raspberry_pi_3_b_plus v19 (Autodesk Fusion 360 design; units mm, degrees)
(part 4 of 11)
sketch "Sketch3" plane through (0, 0, 15.35) normal (0, 0, 1) x axis (-1, 0, 0)
  line L1 (-1.7869, -1.625) -> (-1.7869, -4.375)
  line L2 (-7, -3.5135) -> (-1.5412, -4.3781)
  line L3 (-7, -2.4865) -> (-7, -3.5135)
  line L4 (-1.5412, -1.6219) -> (-7, -2.4865)
  line L5 (-1.7303, -1.625) -> (-1.7303, -4.375)
  line L6 (-7.5, -2.3346) -> (-7.5, -3.6654)
  line L7 (-7.2048, -4.0111) -> (-2, -4.8354)
  line L8 (-2, -1.1646) -> (-7.2048, -1.9889)
  line L9 (-2, -4.8354) -> (-1.75, -4.875)
  line L10 (-1.5803, -4.875) -> (-2, -4.875)
  line L11 (-2, -4.875) -> (-1.5803, -4.875)
  line L12 (-1.75, -1.125) -> (-2, -1.1646)
  line L13 (-1.5803, -1.125) -> (-2, -1.125)
  line L14 (-2, -1.125) -> (-2, -1.1646)
  line L15 (-2, -4.8354) -> (-2, -4.875)
  line L16 (-1.7303, 4.375) -> (-1.7303, 1.625)
  line L17 (-11.6332, 0) -> (0, 0)
  line L18 (-2, 4.875) -> (-1.5803, 4.875)
  line L19 (-2, 4.8354) -> (-2, 4.875)
  line L20 (-2, 1.125) -> (-2, 1.1646)
  line L21 (-1.5803, 1.125) -> (-2, 1.125)
  line L22 (-1.75, 1.125) -> (-2, 1.1646)
  line L23 (-2, 4.8354) -> (-1.75, 4.875)
  line L24 (-7, 3.5135) -> (-1.5412, 4.3781)
  line L25 (-7, 2.4865) -> (-7, 3.5135)
  line L26 (-1.5412, 1.6219) -> (-7, 2.4865)
  line L27 (-5, -2.1697) -> (-5, -3.8303)
  line L28
  line L29 (-2.7476, 1.625) -> (-2.7476, 4.375)
  line L30 (-2.7476, -4.375) -> (-2.7476, -1.625)
  line L31 (-7.2048, 1.9889) -> (-2, 1.1646)
  line L32 (-7.5, 3.6654) -> (-7.5, 2.3346)
  line L33 (-2, 4.8354) -> (-7.2048, 4.0111)
  line L34 (-2.0343, 16.7136) -> (-6.9525, 16.1966)
  line L35 (-1.9, 17.5444) -> (-1.9, 16.8627)
  line L36 (-6.9525, 18.2105) -> (-2.0343, 17.6936)
  line L37 (-6.9525, 18.2105) -> (-6.9525, 16.1966)
  line L38 (-6.9525, 17.2036) -> (-1.9, 17.2036)
  line L39 (-1.8477, 18.1753) -> (-6.8739, 18.7036)
  line L40 (-6.8739, 15.7036) -> (-1.8477, 16.2319)
  line L41 (-1.4, 16.7291) -> (-1.4, 17.6781)
  line L42 (-2.0343, -16.7136) -> (-6.9525, -16.1966)
  line L43 (-1.9, -17.5444) -> (-1.9, -16.8627)
  line L44 (-6.9525, -18.2105) -> (-2.0343, -17.6936)
  line L45 (-6.8739, -18.7036) -> (-1.8477, -18.1753)
  line L46 (-1.4, -17.6781) -> (-1.4, -16.7291)
  line L47 (-1.8477, -16.2319) -> (-6.8739, -15.7036)
  line L48 (-3.3296, -16.2022) -> (-3.3296, -18.205)
  line L49 (-7.9, 19.2786) -> (-7.9, 7.1286)
  line L50 (4.3644, 13.2036) -> (-7.9, 13.2036)
  line L51 (-2.0343, 9.6936) -> (-6.9525, 10.2105)
  line L52 (-1.9, 8.8627) -> (-1.9, 9.5444)
  line L53 (-6.9525, 8.1966) -> (-2.0343, 8.7136)
  line L54 (-6.8739, 7.7036) -> (-1.8477, 8.2319)
  line L55 (-1.4, 8.7291) -> (-1.4, 9.6781)
  line L56 (-1.8477, 10.1753) -> (-6.8739, 10.7036)
  line L57 (-1.4, -9.6781) -> (-1.4, -8.7291)
  line L58 (-6.8739, -10.7036) -> (-1.8477, -10.1753)
  line L59 (-1.8477, -8.2319) -> (-6.8739, -7.7036)
  line L60 (-2.0343, -9.6936) -> (-6.9525, -10.2105)
  line L61 (-1.9, -8.8627) -> (-1.9, -9.5444)
  line L62 (-6.9525, -8.1966) -> (-2.0343, -8.7136)
  line L63 (-2, 21.5718) -> (-2, 21.5322)
  line L64 (-7.2048, 22.3961) -> (-2, 21.5718)
  line L65 (-7.5, 24.0725) -> (-7.5, 22.7418)
  line L66 (-2, 25.2426) -> (-7.2048, 24.4182)
  line L67 (-2, 25.2822) -> (-2, 25.2426)
  line L68 (-1.5803, 25.2822) -> (-2, 25.2822)
  line L69 (-1.7303, 24.7822) -> (-1.5803, 24.7822)
  line L70 (-1.7303, 22.0322) -> (-1.7303, 24.7822)
  line L71 (-1.5803, 22.0322) -> (-1.7303, 22.0322)
  line L72 (-2, 21.5322) -> (-1.5803, 21.5322)
  line L73 (-7.9, 20.9572) -> (-7.9, 26.3572)
  line L74 (-7.9, 20.4572) -> (-7.9, 20.9572)
  line L75 (0.28, 20.4572) -> (-7.9, 20.4572)
  line L76 (0.28, 26.3572) -> (0.28, 20.4572)
  line L77 (-7.9, 26.3572) -> (0.28, 26.3572)
  line L78 (-1.7303, 23.4072) -> (-7.5, 23.4072)
  line L79 (-6.7891, 23.9541) -> (-1.5412, 24.7852)
  line L80 (-7, 23.1072) -> (-7, 23.7071)
  line L81 (-1.5412, 22.0291) -> (-6.7891, 22.8603)
  line L82 (-5, 24.2374) -> (-5, 22.5769)
  line L83 (-1.75, 25.2822) -> (-2, 25.2426)
  line L84 (-1.75, 21.5322) -> (-2, 21.5718)
  line L85 (-2.7476, 22.0322) -> (-2.7476, 24.7822)
  line L86 (-6.7891, -23.9541) -> (-1.5412, -24.7852)
  line L87 (-7, -23.1072) -> (-7, -23.7071)
  line L88 (-1.5412, -22.0291) -> (-6.7891, -22.8603)
  line L89 (-5, -24.2374) -> (-5, -22.5769)
  line L90 (-7.9, -20.9572) -> (-7.9, -20.4572)
  line L91 (-7.9, -26.3572) -> (-7.9, -20.9572)
  line L92 (0.28, -26.3572) -> (-7.9, -26.3572)
  line L93 (0.28, -20.4572) -> (0.28, -26.3572)
  line L94 (-7.9, -20.4572) -> (0.28, -20.4572)
  line L95 (-1.5803, -24.7822) -> (-1.7303, -24.7822)
  line L96 (-2, -25.2822) -> (-1.5803, -25.2822)
  line L97 (-2, -25.2426) -> (-2, -25.2822)
  line L98 (-7.2048, -24.4182) -> (-2, -25.2426)
  line L99 (-7.5, -22.7418) -> (-7.5, -24.0725)
  line L100 (-2, -21.5718) -> (-7.2048, -22.3961)
  line L101 (-2, -21.5322) -> (-2, -21.5718)
  line L102 (-1.5803, -21.5322) -> (-2, -21.5322)
  line L103 (-1.7303, -22.0322) -> (-1.5803, -22.0322)
  line L104 (-1.7303, -24.7822) -> (-1.7303, -22.0322)
  line L105 (-1.75, -25.2822) -> (-2, -25.2426)
  line L106 (-2.7476, -24.7822) -> (-2.7476, -22.0322)
  line L107 (-1.75, -21.5322) -> (-2, -21.5718)
  arc A1 centre (-1.5803, -4.625) radius 0.25 clockwise from (-1.5803, -4.375) to (-1.5803, -4.875)
  arc A2 centre (-1.5803, -4.625) radius 0.25 clockwise from (-1.5803, -4.375) to (-1.5803, -4.875)
  arc A3 centre (-1.5803, -1.375) radius 0.25 clockwise from (-1.5803, -1.125) to (-1.5803, -1.625)
  arc A4 centre (-1.5803, 4.625) radius 0.25 clockwise from (-1.5803, 4.875) to (-1.5803, 4.375)
  arc A5 centre (-1.5803, 1.375) radius 0.25 clockwise from (-1.5803, 1.625) to (-1.5803, 1.125)
  arc A6 centre (-6.75, -3.3) radius 0.25 clockwise from (-6.7891, -3.5469) to (-7, -3.3)
  arc A7 centre (-6.75, -2.7) radius 0.25 clockwise from (-7, -2.7) to (-6.7891, -2.4531)
  arc A8 centre (-6.75, 3.3) radius 0.25 clockwise from (-7, 3.3) to (-6.7891, 3.5469)
  arc A9 centre (-6.75, 2.7) radius 0.25 clockwise from (-6.7891, 2.4531) to (-7, 2.7)
  arc A10 centre (-7.15, -3.6654) radius 0.35 clockwise from (-7.2048, -4.0111) to (-7.5, -3.6654)
  arc A11 centre (-7.15, -2.3346) radius 0.35 clockwise from (-7.5, -2.3346) to (-7.2048, -1.9889)
  arc A12 centre (-7.15, 2.3346) radius 0.35 clockwise from (-7.2048, 1.9889) to (-7.5, 2.3346)
  arc A13 centre (-7.15, 3.6654) radius 0.35 clockwise from (-7.5, 3.6654) to (-7.2048, 4.0111)
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  point P10 (-1.5412, -4.3781)
  point P16 (-1.5412, -1.6219)
  point P21 (-2, -4.8354)
  point P24 (-2, -4.8354)
  point P23 (-1.75, -4.875)
  point P22 (-2, -1.1646)
  point P27 (-2, -1.1646)
  point P28 (-1.75, -1.125)
  point P1 (0, 0)
  point P33 (0, 0)
  point P4 (-1.5803, -4.875)
  point P36 (-1.5803, 4.875)
  point P5 (-1.5803, -4.375)
  point P37 (-1.5803, 4.375)
  point P47 (-1.5412, 4.3781)
  point P11 (-7, -3.5135)
  point P48 (-7, 3.5135)
  point P12 (-7, -2.4865)
  point P49 (-7, 2.4865)
  point P13 (-1.5803, -1.625)
  point P52 (-1.5803, 1.625)
  point P14 (-1.5803, -1.125)
  point P53 (-1.5803, 1.125)
  point P50 (-1.5412, 1.6219)
  point P39 (-2, 4.8354)
  point P40 (-2, 1.1646)
  point P45 (-1.75, 4.875)
  point P46 (-2, 4.8354)
  point P26 (-2, -4.875)
  point P38 (-2, 4.875)
  point P43 (-2, 1.1646)
  point P44 (-1.75, 1.125)
  point P29 (-2, -1.125)
  point P41 (-2, 1.125)
  point P30 (-1.5803, -1.125)
  point P42 (-1.5803, 1.125)
  point P54 (-5, -3.8303)
  point P55 (-5, 3.8303)
  point P56 (-5, -2.1697)
  point P57 (-5, 2.1697)
  point P63 (-7, -3.3)
  point P62 (-6.7891, -3.5469)
  point P66 (-7, -2.7)
  point P65 (-6.7891, -2.4531)
  point P70 (-6.7891, 3.5469)
  point P69 (-7, 3.3)
  point P72 (-6.7891, 2.4531)
  point P73 (-7, 2.7)
  point P90 (-6.9525, 16.1966)
  point P91 (-6.9525, 16.1966)
  point P98 (-6.9525, 18.2105)
  point P99 (-6.9525, 18.2105)
  point P102 (-1.9, 17.2036)
  point P103 (-6.9525, 17.2036)
  point P114 (-6.9525, -16.1966)
  point P92 (-2.0343, 16.7136)
  point P115 (-2.0343, -16.7136)
  point P93 (-1.9, 16.8627)
  point P117 (-1.9, -16.8627)
  point P95 (-1.9, 17.5444)
  point P118 (-1.9, -17.5444)
  point P96 (-2.0343, 17.6936)
  point P120 (-2.0343, -17.6936)
  point P121 (-6.9525, -18.2105)
  point P138 (-7.9, 13.2036)
  point P140 (-6.9525, 10.2105)
  point P141 (-2.0343, 9.6936)
  point P143 (-1.9, 9.5444)
  point P144 (-1.9, 8.8627)
  point P146 (-2.0343, 8.7136)
  point P147 (-6.9525, 8.1966)
  point P172 (-6.9525, -10.2105)
  point P173 (-2.0343, -9.6936)
  point P175 (-1.9, -9.5444)
  point P176 (-1.9, -8.8627)
  point P178 (-2.0343, -8.7136)
  point P179 (-6.9525, -8.1966)
  point P203 (-7.5, 23.4072)
  point P204 (-1.7303, 23.4072)
  point P206 (-6.7891, 23.9541)
  point P210 (-6.7891, 22.8603)
  point P213 (-5, 22.5769)
  point P214 (-5, 24.2374)
  point P188 (-2, 25.2426)
  point P215 (-2, 25.2426)
  point P216 (-1.75, 25.2822)
  point P181 (-2, 21.5718)
  point P217 (-2, 21.5718)
  point P218 (-1.75, 21.5322)
  point P205 (-1.5412, 24.7852)
  point P221 (-1.5412, -24.7852)
  point P222 (-6.7891, -23.9541)
  point P207 (-7, 23.7071)
  point P224 (-7, -23.7071)
  point P209 (-7, 23.1072)
  point P225 (-7, -23.1072)
  point P227 (-6.7891, -22.8603)
  point P212 (-1.5412, 22.0291)
  point P228 (-1.5412, -22.0291)
  point P229 (-5, -22.5769)
  point P230 (-5, -24.2374)
  point P241 (-2, -25.2426)
  point P254 (-2, -25.2426)
  point P255 (-1.75, -25.2822)
  point P248 (-2, -21.5718)
  point P258 (-2, -21.5718)
  point P259 (-1.75, -21.5322)
  coincident A1 P10
  coincident A3 P16
  tangent A3 L4
  vertical L3
  tangent A1 L2
  parallel L2 L7
  parallel L4 L8
  coincident P21 P24
  coincident P23 L10
  parallel L7 L9
  coincident P22 P27
  parallel L8 L12
  coincident P28 L13
  coincident P1 P33
  horizontal L17
  symmetric P4 L17 P36
  symmetric P5 L17 P37
  symmetric A1 L17 A4
  symmetric P10 L17 P47
  symmetric P11 L17 P48
  symmetric P12 L17 P49
  symmetric P13 L17 P52
  symmetric P14 L17 P53
  symmetric A3 L17 A5
  symmetric P16 L17 P50
  symmetric P21 L17 P39
  symmetric P22 L17 P40
  symmetric P23 L17 P45
  symmetric P24 L17 P46
  symmetric P26 L17 P38
  symmetric P27 L17 P43
  symmetric P28 L17 P44
  symmetric P29 L17 P41
  symmetric P30 L17 P42
  coincident L2 P54
  coincident L24 P55
  vertical L27
  collinear L27 L28
  coincident L4 P56
  coincident L26 P57
  tangent L2 A6
  coincident L3 P63
  coincident L2 P62
  tangent L3 A6
  tangent L4 A7
  coincident L3 P66
  coincident L4 P65
  tangent L3 A7
  equal A6 A7
  symmetric L17 P62 P70
  symmetric L17 P63 P69
  symmetric L17 A6 A8
  symmetric L17 P65 P72
  symmetric L17 P66 P73
  symmetric L17 A7 A9
  coincident P90 P91
  vertical L35
  coincident P98 P99
  midpoint L35 P102
  midpoint L37 P103
  horizontal L38
  parallel L36 L39
  parallel L34 L40
  symmetric L17 P91 P114
  symmetric L17 P92 P115
  symmetric L17 P93 P117
  symmetric L17 P95 P118
  symmetric L17 P96 P120
  symmetric L17 P99 P121
  midpoint L49 P138
  horizontal L50
  symmetric P91 L50 P140
  symmetric P92 L50 P141
  symmetric P93 L50 P143
  symmetric P95 L50 P144
  symmetric P96 L50 P146
  symmetric P99 L50 P147
  symmetric L17 P140 P172
  symmetric L17 P141 P173
  symmetric L17 P143 P175
  symmetric L17 P144 P176
  symmetric L17 P146 P178
  symmetric L17 P147 P179
  midpoint L65 P203
  midpoint L70 P204
  vertical L80
  symmetric L78 P206 P210
  coincident L81 P213
  coincident L79 P214
  vertical L82
  collinear L3 L80
  parallel L64 L81
  collinear L27 L82
  coincident P188 P215
  parallel L66 L83
  coincident L68 P216
  coincident P181 P217
  parallel L64 L84
  coincident L72 P218
  symmetric L17 P205 P221
  symmetric L17 P206 P222
  symmetric L17 P207 P224
  symmetric L17 P209 P225
  symmetric L17 P210 P227
  symmetric L17 P212 P228
  symmetric L17 P213 P229
  symmetric L17 P214 P230
  coincident P241 P254
  parallel L98 L105
  coincident L96 P255
  coincident P248 P258
  parallel L100 L107
  coincident L102 P259
  dimension "d58_2" distance L3 L6 = 0.5
  dimension "d62_2" distance L25 L27 = 2
  dimension "d67_3" radius A6 = 0.25
  dimension "d133_2" radius = 0.15
  dimension "d227_2" distance L35 L41 = 0.5
  dimension "d386" radius = 0.25 (= "d67_3")
extrude "Extrude1" cut sketch "Sketch3" no distance stored
extrude "Extrude2" add sketch "Sketch3" profile of L2 L4 L9 L10 L11 L12 L13 L14 L15 L18 L19 L20 L21 L22 L23 L24 L26 L28 L29 L30 L63 L67 L68 L72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 to an object
canvas "Canvas2"
sketch "Sketch4" plane through (0, 0, 15.35) normal (0, 0, 1) x axis (-1, 0, 0)
  line L1 (8.5, -21.1878) -> (0.78, -21.1878)
  line L2 (8.5, -6.6286) -> (8.5, -15.9536)
  line L3 (-7.9, -6.6286) -> (8.5, -6.6286)
  line L4 (-7.9, -7.1286) -> (-7.9, -6.6286)
  line L5 (-7.9, -19.2786) -> (-7.9, -7.1286)
  line L6 (-7.9, -19.7786) -> (-7.9, -19.2786)
  line L7 (0.28, -19.7786) -> (-7.9, -19.7786)
  line L8 (0.78, -21.1878) -> (0.78, -19.7786)
  line L9 (7.9563, -25.2118) -> (8.5, -20.7835)
  line L10 (6.5097, -21.514) -> (6.9637, -25.2118)
  line L11 (2.9803, -21.014) -> (6.2597, -21.014)
  line L12 (2.7303, -21.514) -> (2.7303, -21.264)
  line L13 (2.2763, -25.2118) -> (2.7303, -21.514)
  line L14 (0.78, -21.414) -> (0.78, -23.8331)
  line L15 (0.78, -21.1092) -> (1.2837, -25.2118)
  line L16 (7.46, -21.7371) -> (7.46, -25.1508)
  line L17 (8.5, -25.6508) -> (0.78, -25.6508)
  line L18 (6.5097, -21.514) -> (6.5097, -21.264)
  line L19 (1.78, -21.9964) -> (1.78, -25.1508)
  line L20 (0.78, -21.414) -> (8.5, -21.414)
  line L21 (19.0131, 0) -> (0, 0)
  line L22 (7.9563, 25.2118) -> (8.5, 20.7835)
  line L23 (6.5097, 21.514) -> (6.9637, 25.2118)
  line L24 (6.5097, 21.514) -> (6.5097, 21.264)
  line L25 (2.9803, 21.014) -> (6.2597, 21.014)
  line L26 (2.7303, 21.514) -> (2.7303, 21.264)
  line L27 (2.2763, 25.2118) -> (2.7303, 21.514)
  line L28 (0.78, 21.1092) -> (1.2837, 25.2118)
  line L29 (0.78, 21.414) -> (0.78, 23.8331)
  line L30 (0.78, 23.8331) -> (0.78, 24.3609)
  line L31 (0.78, 24.3609) -> (0.78, 25.6508)
  line L32 (0.78, 25.6508) -> (8.5, 25.6508)
  line L33 (8.5, 25.6508) -> (8.5, 24.3609)
  line L34 (8.5, 24.3609) -> (8.5, 23.8331)
  line L35 (8.5, 21.414) -> (8.5, 23.8331)
  line L36 (8.5, 21.1878) -> (8.5, 21.414)
  line L37 (8.5, -24.3609) -> (8.5, -25.6508)
  line L38 (8.5, -23.8331) -> (8.5, -24.3609)
  line L39 (8.5, -21.414) -> (8.5, -23.8331)
  line L40 (0.78, -25.6508) -> (0.78, -24.3609)
  line L41 (0.78, -24.3609) -> (0.78, -23.8331)
  line L42 (8.5, -21.1878) -> (8.5, -21.414)
  line L43 (-7.9, 26.3572) -> (0.28, 26.3572)
  line L44 (0.28, 26.3572) -> (-7.9, 26.3572)
  line L45 (-4.9, 27.3428) -> (-4.9, 26.3572)
  line L46 (-5.5626, 27.3572) -> (-4.2374, 27.3572)
  line L47 (-4.2929, 26.6611) -> (-4.0642, 27.0572)
  line L48 (-5.5071, 26.6611) -> (-5.7358, 27.0572)
  line L49 (-7.9, 20.9572) -> (-7.9, 26.3572)
  line L50 (-4.15, 26.3572) -> (-4.1962, 26.3763)
  line L51 (-5.65, 26.3572) -> (-5.6038, 26.3763)
  line L52 (-5.7256, -26.3572) -> (-5.7015, -26.3472)
  line L53 (-5.629, -26.1336) -> (-5.8665, -25.7222)
  line L54 (-5.65, -25.3472) -> (-4.15, -25.3472)
  line L55 (-4.171, -26.1336) -> (-3.9335, -25.7222)
  line L56 (-4.0744, -26.3572) -> (-4.0985, -26.3472)
  line L57 (0.28, -26.3572) -> (-7.9, -26.3572)
  line L58 (-4.9, -26.3572) -> (-4.9, -25.3472)
  line L59 (-7.9, -26.3572) -> (-7.9, -20.9572)
  line L60 (-8.5786, 5.45) -> (-9.2286, 5.45)
  line L61 (-9.2286, -5.45) -> (-9.2286, 5.45)
  line L62 (-8.5786, 7.1286) -> (-9.2286, 7.1286)
  line L63 (-9.2286, 7.1286) -> (-9.2286, 19.2786)
  line L64 (-8.5786, 19.2786) -> (-9.2286, 19.2786)
  line L65 (-8.5786, -5.45) -> (-9.2286, -5.45)
  line L66 (-8.5786, -7.1286) -> (-9.2286, -7.1286)
  line L67 (-8.5786, 26.3572) -> (-9.2286, 26.3572)
  line L68 (-9.2286, 26.3572) -> (-9.2286, 20.9572)
  line L69 (-9.2286, 20.9572) -> (-9.2286, 26.3572)
  line L70 (-9.2286, 20.9572) -> (-8.5786, 20.9572)
  line L71 (-8.5786, 20.9572) -> (-9.2286, 20.9572)
  line L72 (-9.2286, -7.1286) -> (-9.2286, -19.2786)
  line L73 (-9.2286, -19.2786) -> (-8.5786, -19.2786)
  line L74 (-9.2286, -19.2786) -> (-9.2286, -7.1286)
  line L75 (-8.5786, -20.9572) -> (-9.2286, -20.9572)
  line L76 (-9.2286, -20.9572) -> (-9.2286, -26.3572)
  line L77 (-9.2286, -26.3572) -> (-8.5786, -26.3572)
  line L78 (-9.2286, -26.3572) -> (-9.2286, -20.9572)
  line L79 (-6.9525, -16.1966) -> (-6.9525, -18.2105)
  line L80 (-1.8477, -16.2319) -> (-6.8739, -15.7036)
  line L81 (-1.4, -17.6781) -> (-1.4, -16.7291)
  line L82 (-6.8739, -18.7036) -> (-1.8477, -18.1753)
  line L83 (-1.8477, -8.2319) -> (-6.8739, -7.7036)
  line L84 (-1.4, -9.6781) -> (-1.4, -8.7291)
  line L85 (-6.8739, -10.7036) -> (-1.8477, -10.1753)
  line L86 (-6.9525, -8.1966) -> (-6.9525, -10.2105)
  line L87 (2.5, -16.3786) -> (2.5, -18.0786)
  line L88 (4.2, -16.3786) -> (2.5, -16.3786)
  line L89 (4.2, -18.0786) -> (4.2, -16.3786)
  line L90 (2.5, -18.0786) -> (4.2, -18.0786)
  line L91 (-3.125, -12.5786) -> (-3.125, -13.8286)
  line L92 (4.225, -12.5786) -> (-3.125, -12.5786)
  line L93 (4.225, -13.8286) -> (4.225, -12.5786)
  line L94 (-3.125, -13.8286) -> (4.225, -13.8286)
  line L95 (6.5, -10.8536) -> (6.5, -13.5536)
  line L96 (7.35, -10.7036) -> (6.65, -10.7036)
  line L97 (7.5, -13.5536) -> (7.5, -10.8536)
  line L98 (6.65, -13.7036) -> (7.35, -13.7036)
  line L99 (2.5, -8.3286) -> (2.5, -10.0286)
  line L100 (4.2, -8.3286) -> (2.5, -8.3286)
  line L101 (4.2, -10.0286) -> (4.2, -8.3286)
  line L102 (2.5, -10.0286) -> (4.2, -10.0286)
  line L103 (8.5, -18.4536) -> (8.5, -21.1878)
  line L104 (8, -16.4536) -> (8, -17.9536)
  line L105 (8.5, 21.1878) -> (8.5, 18.4536)
  line L106 (8.5, -6.6286) -> (8.5, -15.9536)
  line L107 (8.5, 15.9536) -> (8.5, 6.6286)
  line L108 (8.5, -18.4536) -> (8.5, -21.1878)
  line L109 (-7.9, -20.9572) -> (-8.5786, -20.9572)
  line L110 (-7.9, -20.4572) -> (-7.9, -20.9572)
  line L111 (-7.9, -20.9572) -> (-7.9, -20.4572)
  line L112 (-7.9, -19.2786) -> (-8.5786, -19.2786)
  line L113 (-7.9, -7.1286) -> (-8.5786, -7.1286)
  line L114 (-7.9, -5.45) -> (-8.5786, -5.45)
  line L115 (-7.9, -5.45) -> (-7.9, -5.95)
  line L116 (-7.9, 5.45) -> (-8.5786, 5.45)
  line L117 (-7.9, 5.95) -> (-7.9, 5.45)
  line L118 (-7.9, 7.1286) -> (-8.5786, 7.1286)
  line L119 (-7.9, 7.1286) -> (-7.9, 6.6286)
  line L120 (-7.9, 19.2786) -> (-8.5786, 19.2786)
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  point P12 (8.5, -20.7835)
  point P28 (0.78, -21.1092)
  point P15 (7.46, -25.1508)
  point P30 (7.46, -25.1508)
  point P25 (1.78, -25.1508)
  point P34 (1.78, -25.1508)
  point P16 (6.5097, -21.514)
  point P22 (2.7303, -21.514)
  point P1 (0, 0)
  point P37 (0, 0)
  point P39 (8.5, 20.7835)
  point P13 (7.9563, -25.2118)
  point P40 (7.9563, 25.2118)
  point P14 (6.9637, -25.2118)
  point P42 (6.9637, 25.2118)
  point P43 (6.5097, 21.514)
  point P17 (6.2597, -21.014)
  point P46 (6.2597, 21.014)
  point P19 (2.9803, -21.014)
  point P47 (2.9803, 21.014)
  point P20 (2.7303, -21.264)
  point P49 (2.7303, 21.264)
  point P50 (2.7303, 21.514)
  point P23 (2.2763, -25.2118)
  point P51 (2.2763, 25.2118)
  point P24 (1.2837, -25.2118)
  point P53 (1.2837, 25.2118)
  point P54 (0.78, 21.1092)
  point P29 (6.5097, -21.264)
  point P44 (6.5097, 21.264)
  point P71 (-4.9, 26.3572)
  point P73 (-4.1962, 26.3763)
  point P82 (-5.6038, 26.3763)
  point P74 (-4.2929, 26.6611)
  point P81 (-5.5071, 26.6611)
  point P76 (-4.2374, 27.3572)
  point P85 (-5.5626, 27.3572)
  point P79 (-4.0642, 27.0572)
  point P83 (-5.7358, 27.0572)
  point P78 (-5.5626, 27.3572)
  point P87 (-4.15, 26.3572)
  point P88 (-5.65, 26.3572)
  point P105 (-4.9, -25.3472)
  point P106 (-4.9, -26.3572)
  point P90 (-5.7015, -26.3472)
  point P101 (-4.0985, -26.3472)
  point P92 (-5.629, -26.1336)
  point P99 (-4.171, -26.1336)
  point P93 (-5.8665, -25.7222)
  point P98 (-3.9335, -25.7222)
  point P89 (-5.7256, -26.3572)
  point P102 (-4.0744, -26.3572)
  point P119 (-9.2286, 25.8572)
  point P118 (-8.7286, 26.3572)
  point P127 (-9.2286, 21.4572)
  point P126 (-8.7286, 20.9572)
  point P132 (-9.2286, 18.7786)
  point P131 (-8.7286, 19.2786)
  point P135 (-9.2286, 7.6286)
  point P134 (-8.7286, 7.1286)
  point P138 (-9.2286, 4.95)
  point P137 (-8.7286, 5.45)
  point P141 (-9.2286, -4.95)
  point P140 (-8.7286, -5.45)
  point P144 (-9.2286, -7.6286)
  point P143 (-8.7286, -7.1286)
  point P149 (-9.2286, -18.7786)
  point P148 (-8.7286, -19.2786)
  point P153 (-8.7286, -20.9572)
  point P160 (-9.2286, -25.8572)
  point P159 (-8.7286, -26.3572)
  point P154 (-9.2286, -21.4572)
  point P240 (-7.9, -19.4286)
  point P239 (-8.05, -19.2786)
  point P245 (-7.9, -6.9786)
  point P244 (-8.05, -7.1286)
  point P248 (-8.05, -5.45)
  point P255 (-7.9, 5.6)
  point P254 (-8.05, 5.45)
  point P261 (-7.9, 6.9786)
  point P260 (-8.05, 7.1286)
  point P266 (-8.05, 19.2786)
  point P232 (-8.05, -20.9572)
  point P233 (-7.9, -20.8072)
  point P249 (-7.9, -5.6)
  point P94 (-5.65, -25.5972)
  point P97 (-4.15, -25.5972)
  coincident L2 P12
  coincident L14 P28
  horizontal L11
  vertical L12
  coincident P15 P30
  vertical L16
  vertical L18
  coincident P25 P34
  vertical L19
  horizontal P16 P22
  coincident P1 P37
  horizontal L21
  symmetric P12 L21 P39
  symmetric P13 L21 P40
  symmetric P14 L21 P42
  symmetric P16 L21 P43
  symmetric P17 L21 P46
  symmetric P19 L21 P47
  symmetric P20 L21 P49
  symmetric P22 L21 P50
  symmetric P23 L21 P51
  symmetric P24 L21 P53
  symmetric P28 L21 P54
  symmetric P29 L21 P44
  coincident L43 P71
  vertical L45
  horizontal L46
  symmetric L45 P73 P82
  symmetric L45 P74 P81
  symmetric L45 P76 P85
  symmetric L45 P79 P83
  coincident P78 P85
  coincident L43 P87
  coincident L43 P88
  midpoint L54 P105
  coincident L57 P106
  vertical L58
  horizontal L54
  symmetric P90 P101 L58
  symmetric P92 P99 L58
  symmetric P93 P98 L58
  coincident P89 L57
  coincident P102 L57
  coincident P119 L68
  coincident P118 L67
  coincident L68 P127
  coincident P126 L70
  coincident L63 P132
  coincident L64 P131
  coincident L63 P135
  coincident L62 P134
  coincident L61 P138
  coincident L60 P137
  coincident L61 P141
  coincident L65 P140
  coincident P144 L72
  coincident L66 P143
  coincident L72 P149
  coincident P148 L73
  coincident P153 L75
  coincident L76 P160
  coincident P159 L77
  coincident P154 L76
  coincident L6 P240
  coincident P239 L112
  coincident L4 P245
  coincident P244 L113
  coincident P248 L114
  coincident P255 L117
  coincident P254 L116
  coincident P261 L119
  coincident P260 L118
  coincident P266 L120
  coincident P232 L109
  coincident P233 L111
  coincident P249 L115
  dimension "d73_3" angle L9 L16 = 7
  dimension "d74_3" angle L10 L16 = 7 (= "d73_3")
  dimension "d75_2" radius = 0.5
  dimension "d77_1" angle L13 L19 = 7 (= "d73_3")
  dimension "d78_1" angle L15 L19 = 7 (= "d73_3")
  dimension "d79_2" distance L11 L20 = 0.4
  dimension "d80_2" radius = 0.25
  dimension "d81_2" distance P16 L11 = 0.5
  dimension "d82_3" distance L16 L19 = 5.68
  dimension "d86_2" distance L44 L46 = 1
  dimension "d87_2" radius = 0.2
  dimension "d89_3" angle L45 L47 = 30
  dimension "d91_3" distance L45 L49 = 3
  dimension "d92_3" distance P82 P88 = 0.05
  dimension "d93_2" distance P87 P88 = 1.5
  dimension "d94_2" angle L43 L51 = 22.5
  dimension "d98_2" angle L53 L58 = 30
  dimension "d99_2" angle L55 L58 = 30
  dimension "d102_2" radius = 0.25
  dimension "d103_2" radius = 0.25
  dimension "d104_2" radius = 0.15
  dimension "d105_1" radius = 0.15
  dimension "d107_2" distance P90 L54 = 1
  dimension "d108_2" distance P94 P97 = 1.5
  dimension "d111_2" distance P90 L57 = 0.01
  dimension "d112_2" angle L52 L57 = 22.5
  dimension "d113_2" distance L58 L59 = 3
  dimension "d115_1" radius = 0.5
  dimension "d224_1" radius = 0.15 (= "d1_3 / 2")
  dimension "d287_1" distance L2 L19 = 6.72 (= "d3_2 - 10.28 mm")
extrude "Extrude4" cut sketch "Sketch4" no distance stored
extrude "Extrude5" add sketch "Sketch4" to an object
extrude "Extrude6" cut sketch "Sketch4" no distance stored
step "Refold1"
face "EdgeFlange9" FlangeHeight 0.85 (= "1 mm - d1_3 / 2") named "d63_3" FlangeAngle 30 named "d64_3"
face "EdgeFlange10" FlangeHeight 1.75 named "d65_3" FlangeAngle 75 named "d66_2"
face "EdgeFlange18" FlangeHeight 1.5 named "d225_2" FlangeAngle 45 named "d226_1"
face "EdgeFlange15" FlangeHeight 1.5 named "d191_1" FlangeAngle 20 named "d192_2" BendWidth 0.1 named "d282_3" BendDepth 0.15 named "d283_3" BendRemnant 0.6
face "EdgeFlange16" FlangeHeight 0.601 (= "2 * d1_3 + 0.001 mm") named "d193_2" FlangeAngle 45 named "d194_1" BendWidth 0.05 named "d195_2" BendDepth 0 named "d196_1" BendRemnant 0 named "d197_1"
face "EdgeFlange17" FlangeHeight 3.0015 named "d200_1" FlangeAngle 45 named "d201_1"
step "Unfold2"
extrude "Extrude3" cut sketch "Sketch3" no distance stored
step "Refold2"
sketch "Sketch1" plane through (-8.5, 0, 0) normal (-1, 0, 0) x axis (0, -1, 0)
  line L1 (-6.25, 14.75) -> (-6.25, 5.425)
  line L2 (-6.55, 14.75) -> (-6.25, 14.75)
  line L3 (-6.55, 5.425) -> (-6.55, 14.75)
  line L4 (6.85, 3.3) -> (5.875, 3.3)
  line L5 (5.875, 2.6127) -> (5.875, 1.5)
  line L6 (6.85, 5.05) -> (6.85, 3.3)
  line L7 (5.875, 5.05) -> (6.85, 5.05)
  line L8 (-5.65, 13.04) -> (-5.65, 14.7)
  line L9 (5.65, 14.7) -> (5.65, 13.04)
  line L10 (-5.65, 14.7) -> (5.65, 14.7)
  line L11 (5.74, 12.95) -> (5.74, 5.6179)
  line L12 (5.875, 1.5) -> (-5.875, 1.5)
  line L13 (-5.875, 1.5) -> (-5.875, 2.6127)
  line L14 (-5.74, 5.6179) -> (-5.74, 12.95)
  line L15 (-5.875, 3.3) -> (-6.85, 3.3)
  line L16 (-6.85, 5.05) -> (-5.875, 5.05)
  line L17 (-6.85, 3.3) -> (-6.85, 5.05)
  line L18 (0, 1.5) -> (0, 14.7)
  line L19 (-3.7701, 15.05) -> (3.7701, 15.05)
  line L20 (6.55, 14.25) -> (6.55, 2.1)
  line L21 (-6.25, 5.425) -> (-6.55, 5.425)
  line L22 (-6.25, 0.5951) -> (-6.55, 0.5951)
  line L23 (-6.25, 2.925) -> (-6.25, 0.5951)
  line L24 (-6.55, 2.925) -> (-6.25, 2.925)
  line L25 (-6.55, 0.5951) -> (-6.55, 2.925)
  arc A1 centre (-5.875, 3) radius 0.3 clockwise from (-5.875, 3.3) to (-5.8, 2.7095)
  arc A2 centre (-5.775, 2.6127) radius 0.1 clockwise from (-5.875, 2.6127) to (-5.8, 2.7095)
  arc A3 centre (5.875, 3) radius 0.3 clockwise from (5.8, 2.7095) to (5.875, 3.3)
  arc A4 centre (5.775, 2.6127) radius 0.1 clockwise from (5.8, 2.7095) to (5.875, 2.6127)
  arc A5 centre (-5.875, 5.35) radius 0.3 clockwise from (-5.74, 5.6179) to (-5.875, 5.05)
  arc A6 centre (5.875, 5.35) radius 0.3 clockwise from (5.875, 5.05) to (5.74, 5.6179)
  arc A7 centre (-5.74, 13.04) radius 0.09 clockwise from (-5.65, 13.04) to (-5.74, 12.95)
  arc A8 centre (5.74, 13.04) radius 0.09 clockwise from (5.74, 12.95) to (5.65, 13.04)
  point P24 (0, 14.7)
  point P25 (0, 1.5)
  point P1 (0, 0)
  point P10 (-5.74, 12.95)
  point P14 (5.74, 12.95)
  point P19 (5.74, 5.6179)
  point P20 (-5.74, 5.6179)
  point P11 (-6.85, 5.05)
  point P23 (6.85, 5.05)
  point P15 (-6.85, 3.3)
  point P18 (6.85, 3.3)
  point P28 (6.85, 4.175)
  point P31 (6.55, 8.175)
  point P8 (-5.875, 2.6127)
  point P38 (-5.875, 2.6127)
  point P37 (-5.875, 3)
  point P7 (-5.875, 3.3)
  point P42 (5.875, 3.3)
  point P36 (-5.8, 2.7095)
  point P41 (5.8, 2.7095)
  point P44 (5.875, 2.6127)
  point P17 (5.875, 2.6127)
  point P46 (-5.875, 5.35)
  point P45 (-5.74, 5.6179)
  point P47 (5.875, 5.35)
  point P48 (-5.74, 12.95)
  point P49 (-5.74, 13.04)
  point P51 (5.74, 13.04)
  point P9 (-5.875, 1.5)
  point P12 (5.875, 1.5)
  point P30 (6.55, 14.25)
  horizontal L10
  vertical L8
  vertical L14
  vertical L17
  horizontal L12
  vertical L11
  vertical L9
  vertical L13
  vertical L5
  vertical L6
  perpendicular L15 L17
  perpendicular L16 L17
  perpendicular L4 L6
  perpendicular L6 L7
  midpoint L10 P24
  midpoint L12 P25
  vertical L18
  vertical P1 P25
  symmetric P10 P14 L18
  symmetric P19 P20 L18
  symmetric P11 P23 L18
  symmetric P15 P18 L18
  midpoint L6 P28
  midpoint L20 P31
  tangent L15 A1
  tangent A1 A2
  coincident P8 P38
  coincident L13 P37
  tangent L13 A2
  symmetric P7 L18 P42
  symmetric L18 P36 P41
  symmetric L18 A1 A3
  symmetric L18 P38 P44
  symmetric L18 A2 A4
  coincident P17 P44
  tangent L16 A5
  coincident L13 P46
  equal A1 A5
  coincident P20 P45
  tangent L7 A6
  equal A1 A6
  symmetric L18 P46 P47
  tangent L8 A7
  coincident P10 P48
  tangent L9 A8
  coincident L14 P49
  coincident L11 P51
  dimension "d141_1" distance L10 L12 = 13.2
  dimension "d147_1" distance L4 L7 = 1.75
  dimension "d153_2" distance P9 P12 = 11.75
  dimension "d156_2" distance L6 L17 = 13.7 (= "13.10 mm + 2 * d1_3")
  dimension "d158_2" distance L1 L8 = 0.6 (= "2 * d1_3")
  dimension "d159_2" distance L10 L19 = 0.35 (= "d1_3 + 0.05 mm")
  dimension "d175_1" distance P28 P31 = 4
  dimension "d208_2" radius A1 = 0.3 (= "d1_3")
  dimension "d209_2" radius A2 = 0.1
  dimension "d217_1" distance P14 P30 = 0.81 (= "2.7 * d1_3")
  dimension "d218_2" distance P14 L10 = 1.75
face "Face1" sketch "Sketch1"
face "EdgeFlange3" FlangeHeight 1.5 named "d168_1" FlangeAngle 90 named "d169_1" BendRadius 0.2 named "d170_2"
face "EdgeFlange4" FlangeHeight 2.5 named "d214_2" FlangeAngle 90 named "d215_2" BendRemnant 0.6 named "d219_1" BendRadius 0.2 named "d220_1"
face "EdgeFlange5" FlangeHeight 2 named "d221_1" FlangeAngle 90 named "d222_1"
base_feature "Base Feature1"
work_plane "WorkPlane1" AlongDistance 8.05 named "d228_2"
sketch "Sketch1" plane through (8.05, 0, 0) normal (1, 0, 0) x axis (0, 1, 0)
  line L1 (-6.2, 9.975) -> (6.2, 9.975)
  line L2 (-6.2, 6.375) -> (-6.2, 9.975)
  line L3 (6.2, 6.375) -> (-6.2, 6.375)
  line L4 (6.2, 9.975) -> (6.2, 6.375)
  line L5 (-6.2, 6.375) -> (6.2, 9.975)
  line L6 (6.2, 6.375) -> (-6.2, 9.975)
  line L7 (-4.6, 7.675) -> (-1.1, 7.675)
  line L8 (-4.6, 8.675) -> (-4.6, 7.675)
  line L9 (-1.1, 8.675) -> (-4.6, 8.675)
  line L10 (-1.1, 7.675) -> (-1.1, 8.675)
  line L11 (-4.6, 8.675) -> (-1.1, 7.675)
  line L12 (-1.1, 8.675) -> (-4.6, 7.675)
  line L13 (0, 9.4362) -> (0, 8.175)
  line L14 (1.1, 8.675) -> (4.6, 8.675)
  line L15 (1.1, 7.675) -> (1.1, 8.675)
  line L16 (4.6, 7.675) -> (1.1, 7.675)
  line L17 (4.6, 8.675) -> (4.6, 7.675)
  point P6 (0, 8.175)
  point P1 (0, 0)
  point P7 (-6.55, 8.175)
  point P12 (-2.85, 8.175)
  point P13 (0, 8.175)
  point P8 (-1.1, 7.675)
  point P17 (1.1, 7.675)
  point P9 (-4.6, 7.675)
  point P18 (4.6, 7.675)
  point P10 (-4.6, 8.675)
  point P15 (4.6, 8.675)
  point P11 (-1.1, 8.675)
  point P16 (1.1, 8.675)
  point P4 (-6.2, 6.375)
  point P5 (6.2, 6.375)
  point P3 (-6.2, 9.975)
  perpendicular L1 L2
  parallel L1 L3
  parallel L2 L4
  horizontal L1
  coincident L5 P6
  coincident L6 P6
  vertical P1 P6
  horizontal P6 P7
  perpendicular L7 L8
  parallel L7 L9
  parallel L8 L10
  horizontal L7
  coincident L11 P12
  coincident L12 P12
  coincident P6 P13
  vertical L13
  symmetric P8 L13 P17
  symmetric P9 L13 P18
  symmetric P10 L13 P15
  symmetric P11 L13 P16
  horizontal P6 P12
  dimension "d229_2" distance P4 P5 = 12.4
  dimension "d230_1" distance P3 P4 = 3.6 (= "3 mm + d1_3 * 2")
  dimension "d231_1" distance P10 P11 = 3.5
  dimension "d232_2" distance P9 P10 = 1
  dimension "d233_2" distance L10 L13 = 1.1
face "Face1" sketch "Sketch1"
face "EdgeFlange2" FlangeHeight 8.5 named "d234_2" FlangeAngle 90 named "d235_2"
extrude "Extrude6" cut sketch "Sketch1" profile of L7 L8 L9 L10 L14 L15 L16 L17 no distance stored
face "EdgeFlange3" FlangeHeight 2.5 named "d236_2" FlangeAngle 20 named "d237_2" BendRemnant 0 named "d240_2" BendWidth 0.01 named "d243_2" BendDepth 0 named "d244_2"
face "EdgeFlange4" FlangeHeight 1 named "d241_2" FlangeAngle 20 (= "d237_2") named "d242_2"
sketch "Sketch3" plane through (0, 0, 9.975) normal (0, 0, 1) x axis (-1, 0, 0)
  line L1 (-7.75, -6.2) -> (-7.75, 6.2)
  line L2 (0.15, -6.2) -> (-7.75, -6.2)
  line L3 (0.15, 6.2) -> (0.15, -6.2)
  line L4 (-7.75, 6.2) -> (0.15, 6.2)
  line L5 (-7.35, -2.132) -> (-7.35, -3.868)
  line L6 (-7.0487, -4.2146) -> (-2.35, -4.875)
  line L7 (-2.35, -3) -> (-7.35, -3)
  line L8 (-2.35, -1.125) -> (-2.35, -4.875)
  line L9 (-7.0487, -1.7854) -> (-2.35, -1.125)
  line L10 (-8.35, 6.2) -> (-8.35, -6.2)
  line L11 (-13, 0) -> (0, 0)
  line L12 (-7.0487, 1.7854) -> (-2.35, 1.125)
  line L13 (-7.35, 2.132) -> (-7.35, 3.868)
  line L14 (-7.0487, 4.2146) -> (-2.35, 4.875)
  line L15 (-2.35, 1.125) -> (-2.35, 4.875)
  arc A1 centre (-7, -3.868) radius 0.35 clockwise from (-7.0487, -4.2146) to (-7.35, -3.868)
  arc A2 centre (-7, -2.132) radius 0.35 clockwise from (-7.35, -2.132) to (-7.0487, -1.7854)
  arc A3 centre (-7, 2.132) radius 0.35 clockwise from (-7.0487, 1.7854) to (-7.35, 2.132)
  arc A4 centre (-7, 3.868) radius 0.35 clockwise from (-7.35, 3.868) to (-7.0487, 4.2146)
  point P14 (-2.35, -1.125)
  point P15 (-2.35, -4.875)
  point P16 (-2.35, -1.125)
  point P7 (-7.35, -3)
  point P6 (-7.0487, -1.7854)
  point P12 (-7.0487, -4.2146)
  point P17 (-2.35, -3)
  point P1 (0, 0)
  point P21 (0, 0)
  point P24 (-7.0487, 1.7854)
  point P10 (-7.35, -3.868)
  point P27 (-7.35, 3.868)
  point P29 (-7.0487, 4.2146)
  point P13 (-7.35, -2.132)
  point P26 (-7.35, 2.132)
  point P23 (-2.35, 1.125)
  point P30 (-2.35, 4.875)
  point P31 (-2.35, 1.125)
  point P9 (-2.35, 3)
  symmetric P14 P15 L7
  coincident P14 P16
  coincident P7 L5
  tangent L6 A1
  tangent L5 A1
  tangent L5 A2
  tangent A2 L9
  equal A1 A2
  symmetric P6 P12 L7
  coincident P17 L8
  coincident P1 P21
  horizontal L11
  symmetric P6 L11 P24
  symmetric P10 L11 P27
  symmetric P12 L11 P29
  symmetric P13 L11 P26
  symmetric P14 L11 P23
  symmetric P15 L11 P30
  symmetric P16 L11 P31
  symmetric A1 L11 A4
  symmetric A2 L11 A3
  midpoint P9 L15
  dimension "d260_2" distance P9 L7 = 6
  dimension "d261_1" angle L6 L8 = 82
  dimension "d262_1" radius A1 = 0.35
  dimension "d263_1" distance L5 L8 = 5
  dimension "d264_3" distance P15 P16 = 3.75
  dimension "d265_3" distance L5 L10 = 1
extrude "Extrude2" cut sketch "Sketch3" profile of L5 L6 A1 L8 A2 L9 L12 A3 L13 A4 L14 L15 no distance stored
face "EdgeFlange6" FlangeHeight 2.5 named "d267_3" FlangeAngle 10 named "d268_3" BendWidth 0.5 named "d269_3" BendDepth 0.3 named "d270_3" BendRemnant 0.6 named "d271_3"
step "Unfold2"
sketch "Sketch4" plane through (8.35, 0, 0) normal (1, 0, 0) x axis (0, 1, 0)
  line L1 (6.2, 6.975) -> (-6.2, 6.975)
  line L2 (6.2, 9.375) -> (6.2, 6.975)
  line L3 (-6.2, 9.375) -> (6.2, 9.375)
  line L4 (-6.2, 6.975) -> (-6.2, 9.375)
  line L5 (-3.7536, 11.1257) -> (-4.3774, 15.5646)
  line L6 (-2.4445, 10.9536) -> (-3.5555, 10.9536)
  line L7 (-1.6226, 15.5646) -> (-2.2464, 11.1257)
  line L8 (-1.7854, 10.7549) -> (-1.1601, 15.2036)
  line L9 (-4.8399, 15.2036) -> (-4.2146, 10.7549)
  line L10 (-3.868, 10.4536) -> (-2.132, 10.4536)
  line L11 (-4.875, 15.4536) -> (-4.8399, 15.2036)
  line L12 (-4.875, 15.5298) -> (-4.875, 15.2036)
  line L13 (-4.875, 15.2036) -> (-4.875, 15.5298)
  line L14 (-4.875, 15.2036) -> (-4.8399, 15.2036)
  line L15 (-1.125, 15.4536) -> (-1.1601, 15.2036)
  line L16 (-1.125, 15.2036) -> (-1.125, 15.5298)
  line L17 (-1.125, 15.5298) -> (-1.125, 15.2036)
  line L18 (-1.1601, 15.2036) -> (-1.125, 15.2036)
  line L19 (0, 22.1983) -> (0, 0)
  line L20 (4.875, 15.2036) -> (4.875, 15.5298)
  line L21 (1.125, 15.5298) -> (1.125, 15.2036)
  line L22 (1.125, 15.2036) -> (1.1601, 15.2036)
  line L23 (4.8399, 15.2036) -> (4.875, 15.2036)
  line L24 (1.1601, 15.2036) -> (1.125, 15.2036)
  line L25 (1.1601, 15.2036) -> (1.7854, 10.7549)
  line L26 (2.132, 10.4536) -> (3.868, 10.4536)
  line L27 (4.2146, 10.7549) -> (4.8399, 15.2036)
  line L28 (1.125, 15.4536) -> (1.1601, 15.2036)
  line L29 (4.875, 15.4536) -> (4.8399, 15.2036)
  line L30 (3.7536, 11.1257) -> (4.3774, 15.5646)
  line L31 (2.4445, 10.9536) -> (3.5555, 10.9536)
  line L32 (1.6226, 15.5646) -> (2.2464, 11.1257)
  line L33 (6.2, 8.175) -> (-6.2, 8.175)
  line L34 (-3.7536, 5.2243) -> (-4.3774, 0.7854)
  line L35 (-2.4445, 5.3964) -> (-3.5555, 5.3964)
  line L36 (-1.6226, 0.7854) -> (-2.2464, 5.2243)
  line L37 (3.7536, 5.2243) -> (4.3774, 0.7854)
  line L38 (2.4445, 5.3964) -> (3.5555, 5.3964)
  line L39 (1.6226, 0.7854) -> (2.2464, 5.2243)
  line L40 (-4.875, 0.8964) -> (-4.8399, 1.1464)
  line L41 (-1.125, 0.8964) -> (-1.1601, 1.1464)
  line L42 (1.125, 0.8964) -> (1.1601, 1.1464)
  line L43 (4.875, 0.8964) -> (4.8399, 1.1464)
  line L44 (-4.875, 1.1464) -> (-4.875, 0.8202)
  line L45 (-4.8399, 1.1464) -> (-4.875, 1.1464)
  line L46 (-4.2146, 5.5951) -> (-4.8399, 1.1464)
  line L47 (-1.1601, 1.1464) -> (-1.7854, 5.5951)
  line L48 (-1.125, 0.8202) -> (-1.125, 1.1464)
  line L49 (-1.125, 1.1464) -> (-1.1601, 1.1464)
  line L50 (-2.132, 5.8964) -> (-3.868, 5.8964)
  line L51 (1.125, 1.1464) -> (1.125, 0.8202)
  line L52 (1.1601, 1.1464) -> (1.125, 1.1464)
  line L53 (1.7854, 5.5951) -> (1.1601, 1.1464)
  line L54 (4.875, 0.8202) -> (4.875, 1.1464)
  line L55 (4.875, 1.1464) -> (4.8399, 1.1464)
  line L56 (4.8399, 1.1464) -> (4.2146, 5.5951)
  line L57 (3.868, 5.8964) -> (2.132, 5.8964)
  arc A1 centre (-3.5555, 11.1536) radius 0.2 clockwise from (-3.5555, 10.9536) to (-3.7536, 11.1257)
  arc A2 centre (-2.4445, 11.1536) radius 0.2 clockwise from (-2.2464, 11.1257) to (-2.4445, 10.9536)
  arc A3 centre (-4.625, 15.5298) radius 0.25 clockwise from (-4.875, 15.5298) to (-4.375, 15.5298)
  arc A4 centre (-1.375, 15.5298) radius 0.25 clockwise from (-1.625, 15.5298) to (-1.125, 15.5298)
  arc A5 centre (-1.375, 15.5298) radius 0.25 clockwise from (-1.625, 15.5298) to (-1.125, 15.5298)
  arc A6 centre (-3.868, 10.8036) radius 0.35 clockwise from (-3.868, 10.4536) to (-4.2146, 10.7549)
  arc A7 centre (-2.132, 10.8036) radius 0.35 clockwise from (-1.7854, 10.7549) to (-2.132, 10.4536)
  arc A8 centre (1.375, 15.5298) radius 0.25 clockwise from (1.125, 15.5298) to (1.625, 15.5298)
  arc A9 centre (4.625, 15.5298) radius 0.25 clockwise from (4.375, 15.5298) to (4.875, 15.5298)
  arc A10 centre (2.132, 10.8036) radius 0.35 clockwise from (2.132, 10.4536) to (1.7854, 10.7549)
  arc A11 centre (3.868, 10.8036) radius 0.35 clockwise from (4.2146, 10.7549) to (3.868, 10.4536)
  arc A12 centre (3.5555, 11.1536) radius 0.2 clockwise from (3.7536, 11.1257) to (3.5555, 10.9536)
  arc A13 centre (2.4445, 11.1536) radius 0.2 clockwise from (2.4445, 10.9536) to (2.2464, 11.1257)
  arc A14 centre (-3.5555, 5.1964) radius 0.2 clockwise from (-3.7536, 5.2243) to (-3.5555, 5.3964)
  arc A15 centre (-2.4445, 5.1964) radius 0.2 clockwise from (-2.4445, 5.3964) to (-2.2464, 5.2243)
  arc A16 centre (3.5555, 5.1964) radius 0.2 clockwise from (3.5555, 5.3964) to (3.7536, 5.2243)
  arc A17 centre (2.4445, 5.1964) radius 0.2 clockwise from (2.2464, 5.2243) to (2.4445, 5.3964)
  arc A18 centre (-4.625, 0.8202) radius 0.25 clockwise from (-4.375, 0.8202) to (-4.875, 0.8202)
  arc A19 centre (-1.375, 0.8202) radius 0.25 clockwise from (-1.125, 0.8202) to (-1.625, 0.8202)
  arc A20 centre (-2.132, 5.5464) radius 0.35 clockwise from (-2.132, 5.8964) to (-1.7854, 5.5951)
  arc A21 centre (-3.868, 5.5464) radius 0.35 clockwise from (-4.2146, 5.5951) to (-3.868, 5.8964)
  arc A22 centre (1.375, 0.8202) radius 0.25 clockwise from (1.625, 0.8202) to (1.125, 0.8202)
  arc A23 centre (4.625, 0.8202) radius 0.25 clockwise from (4.875, 0.8202) to (4.375, 0.8202)
  arc A24 centre (2.132, 5.5464) radius 0.35 clockwise from (1.7854, 5.5951) to (2.132, 5.8964)
  arc A25 centre (3.868, 5.5464) radius 0.35 clockwise from (3.868, 5.8964) to (4.2146, 5.5951)
  point P17 (-4.8399, 15.2036)
  point P20 (-4.8399, 15.2036)
  point P21 (-4.875, 15.4536)
  point P6 (-4.3774, 15.5646)
  point P13 (-1.6226, 15.5646)
  point P14 (-1.1601, 15.2036)
  point P34 (-1.1601, 15.2036)
  point P35 (-1.125, 15.4536)
  point P1 (0, 0)
  point P38 (0, 0)
  point P53 (1.1601, 15.2036)
  point P60 (1.1601, 15.2036)
  point P51 (4.8399, 15.2036)
  point P62 (4.8399, 15.2036)
  point P63 (4.875, 15.4536)
  point P61 (1.125, 15.4536)
  point P64 (4.3774, 15.5646)
  point P7 (-3.7536, 11.1257)
  point P65 (3.7536, 11.1257)
  point P8 (-3.5555, 10.9536)
  point P67 (3.5555, 10.9536)
  point P10 (-2.4445, 10.9536)
  point P68 (2.4445, 10.9536)
  point P11 (-2.2464, 11.1257)
  point P70 (2.2464, 11.1257)
  point P71 (1.6226, 15.5646)
  point P72 (-6.2, 8.175)
  point P73 (6.2, 8.175)
  point P74 (-4.3774, 0.7854)
  point P75 (-3.7536, 5.2243)
  point P77 (-3.5555, 5.3964)
  point P78 (-2.4445, 5.3964)
  point P80 (-2.2464, 5.2243)
  point P81 (-1.6226, 0.7854)
  point P90 (-4.8399, 1.1464)
  point P91 (-4.875, 0.8964)
  point P92 (-1.1601, 1.1464)
  point P93 (-1.125, 0.8964)
  point P94 (1.1601, 1.1464)
  point P95 (1.125, 0.8964)
  point P96 (4.8399, 1.1464)
  point P97 (4.875, 0.8964)
  point P82 (4.3774, 0.7854)
  point P83 (3.7536, 5.2243)
  point P85 (3.5555, 5.3964)
  point P86 (2.4445, 5.3964)
  point P88 (2.2464, 5.2243)
  point P89 (1.6226, 0.7854)
  tangent L5 A1
  tangent L6 A2
  parallel L7 L8
  parallel L5 L9
  parallel L6 L10
  tangent A2 L7
  tangent A1 L6
  coincident P17 P20
  parallel L9 L11
  coincident P21 L12
  coincident P6 A3
  tangent L5 A3
  coincident P13 A4
  tangent L7 A5
  coincident P14 P34
  parallel L8 L15
  coincident P35 L16
  coincident P1 P38
  vertical L19
  equal A1 A2
  coincident P53 P60
  parallel L25 L28
  coincident P51 P62
  parallel L27 L29
  coincident L20 P63
  coincident L21 P61
  symmetric P6 L19 P64
  symmetric P7 L19 P65
  symmetric P8 L19 P67
  symmetric A1 L19 A12
  symmetric P10 L19 P68
  symmetric P11 L19 P70
  symmetric A2 L19 A13
  symmetric P13 L19 P71
  midpoint L4 P72
  midpoint L2 P73
  symmetric P6 L33 P74
  symmetric P7 L33 P75
  symmetric P8 L33 P77
  symmetric A1 L33 A14
  symmetric P10 L33 P78
  symmetric P11 L33 P80
  symmetric A2 L33 A15
  symmetric P13 L33 P81
  symmetric P20 L33 P90
  symmetric P21 L33 P91
  symmetric P34 L33 P92
  symmetric P35 L33 P93
  symmetric P60 L33 P94
  symmetric P61 L33 P95
  symmetric P62 L33 P96
  symmetric P63 L33 P97
  symmetric P64 L33 P82
  symmetric P65 L33 P83
  symmetric P67 L33 P85
  symmetric A12 L33 A16
  symmetric P68 L33 P86
  symmetric P70 L33 P88
  symmetric A13 L33 A17
  symmetric P71 L33 P89
  dimension "d272_3" distance L6 L10 = 0.5
  dimension "d273_3" radius A1 = 0.2
extrude "Extrude3" add sketch "Sketch4" profile of L11 L12 L13 L14 L15 L16 L17 L18 L20 L21 L22 L23 L24 L28 L29 L40 L41 L42 L43 L44 L45 L48 L49 L51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 against normal blind 0.3 named "d274_3"
extrude "Extrude4" cut sketch "Sketch4" profile of L5 A1 L6 A2 L7 L8 L9 L10 L11 L12 L13 A3 A4 A5 L15 L16 L17 A6 A7 A8 A9 L20 L21 L25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 no distance stored
step "Refold2"
face "EdgeFlange7" FlangeHeight 0.75 named "d277_3" FlangeAngle 30 named "d278_3"
face "EdgeFlange8" FlangeHeight 2 named "d279_3" FlangeAngle 72 named "d280_3"
step "Unfold3"
extrude "Extrude5" cut sketch "Sketch4" profile of L5 A1 L6 A2 L7 L8 L9 L10 L11 L12 L13 A3 A4 A5 L15 L16 L17 A6 A7 A8 A9 L20 L21 L25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 no distance stored
step "Refold3"
work_plane "WorkPlane1" AlongDistance -15.76 (= "-10.28 mm - 2.71 mm - 2.62 mm - 0.15 mm") named "d288_1"
sketch "Sketch1" plane through (-7.26, 0, 15.975) normal (1, 0, 0) x axis (0, 1, 0)
  line L1 (3.8, -18.2428) -> (3.5893, -18.775)
  line L2 (3.8, -2.175) -> (3.8, -13.7834)
  line L3 (3.2, -13.7834) -> (3.2, -2.175)
  line L4 (3.8, -15.1666) -> (3.8, -18.2428)
  line L5 (3.9928, -14.3132) -> (3.8, -14.475)
  line L6 (3.2, -18.2533) -> (3.2, -15.1666)
  line L7 (3.2, -2.175) -> (3.8, -2.175)
  line L8 (3.5893, -18.775) -> (3.4107, -18.775)
  line L9 (3.4107, -18.775) -> (3.2, -18.2533)
  line L10 (3.7701, -0.925) -> (-3.7701, -0.925)
  line L11 (3.5, -18.775) -> (3.5, -2.175)
  line L12 (3.2, -14.475) -> (3.8, -14.475)
  line L13 (3.9928, -14.6368) -> (3.8, -14.475)
  line L14 (3.0072, -14.3132) -> (3.2, -14.475)
  line L15 (3.0072, -14.6368) -> (3.2, -14.475)
  arc A1 centre (3.8, -14.0834) radius 0.3 clockwise from (3.8, -13.7834) to (3.9928, -14.3132)
  arc A2 centre (3.8, -14.8666) radius 0.3 clockwise from (3.9928, -14.6368) to (3.8, -15.1666)
  arc A3 centre (3.2, -14.0834) radius 0.3 clockwise from (3.0072, -14.3132) to (3.2, -13.7834)
  arc A4 centre (3.2, -14.8666) radius 0.3 clockwise from (3.2, -15.1666) to (3.0072, -14.6368)
  point P5 (3.8, -14.0834)
  point P8 (3.8, -14.475)
  point P6 (3.9928, -14.3132)
  point P9 (3.9928, -14.3132)
  point P19 (3.5, -2.175)
  point P20 (3.5, -18.775)
  point P23 (3.9928, -14.6368)
  point P25 (3.8, -14.475)
  point P26 (3.9928, -14.6368)
  point P14 (3.8, -13.7834)
  point P24 (3.8, -15.1666)
  point P13 (3.8, -15.1666)
  point P28 (3.0072, -14.3132)
  point P30 (3.2, -14.475)
  point P31 (3.0072, -14.3132)
  point P29 (3.2, -13.7834)
  point P36 (3.0072, -14.6368)
  point P35 (3.2, -15.1666)
  point P32 (3.2, -14.475)
  point P33 (3.0072, -14.6368)
  point P4 (3.2, -13.7834)
  point P12 (3.2, -15.1666)
  point P21 (3.2, -14.475)
  point P18 (0, -15.975)
  point P1 (0, 0)
  vertical L3
  vertical L2
  coincident P5 L2
  coincident P8 L2
  collinear L2 L4
  collinear L3 L6
  horizontal L8
  horizontal L7
  coincident P6 P9
  tangent A1 L5
  midpoint L7 P19
  midpoint L8 P20
  horizontal L12
  symmetric P6 L12 P23
  symmetric P8 L12 P25
  symmetric P9 L12 P26
  symmetric P14 L12 P24
  symmetric A1 L12 A2
  coincident P23 P26
  coincident P13 P24
  coincident P8 P25
  symmetric P6 L11 P28
  symmetric P8 L11 P30
  symmetric P9 L11 P31
  symmetric P14 L11 P29
  symmetric A1 L11 A3
  symmetric L11 P23 P36
  symmetric L11 P24 P35
  symmetric L11 A2 A4
  symmetric L11 P25 P32
  symmetric L11 P26 P33
  coincident P4 P29
  coincident P12 P35
  coincident P21 P30
  dimension "d289_1" distance L2 L3 = 0.6
  dimension "d293_1" distance L7 L10 = 1.25
  dimension "d295_1" distance L8 P18 = 2.8
  dimension "d298_1" angle L2 L5 = 50
  dimension "d299_1" radius A1 = 0.3
  dimension "d300_1" distance P18 L12 = 1.5
  dimension "d301_1" distance P1 L11 = 3.5 (= "( 7 / 2 ) * 1 mm")
face "Face1" sketch "Sketch1"
face "EdgeFlange2" FlangeHeight 4 named "d302_1" FlangeAngle 90 named "d303_1"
